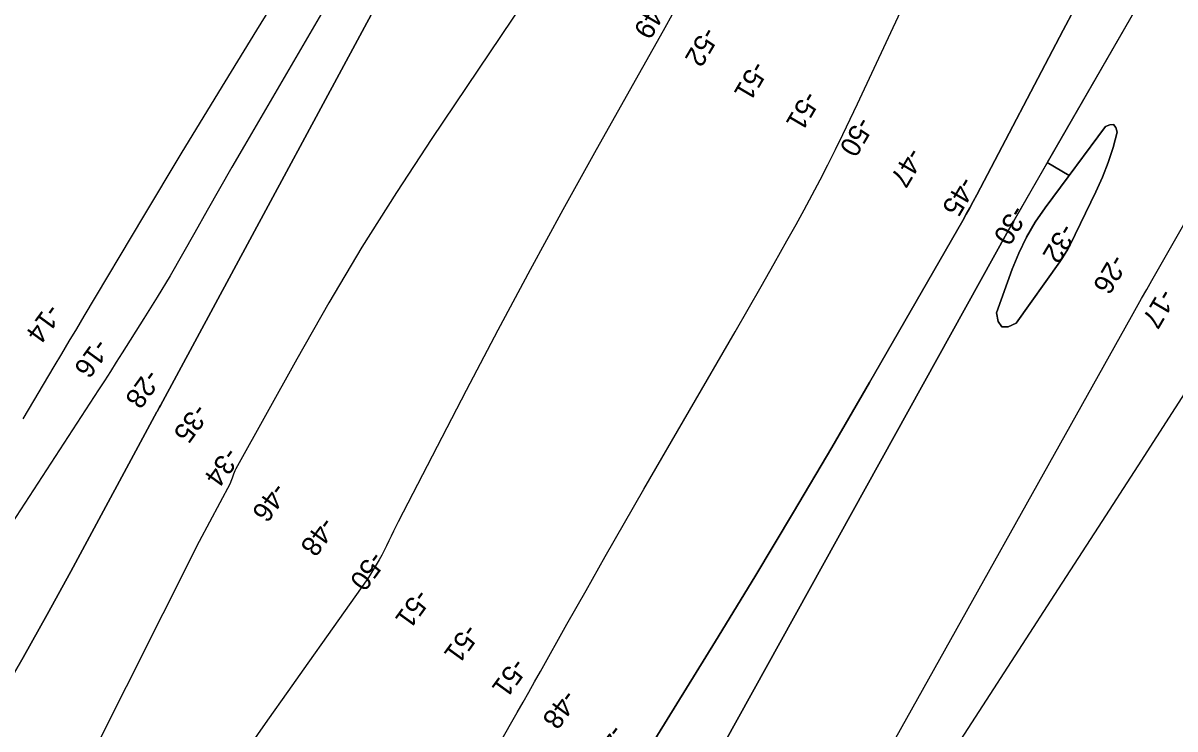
# Model space of a CAD drawing. Extents: x 3888273 to 3909528, y 158682 to 181032.
# Drawn here: x 3897168 to 3899111, y 165430 to 166620 of the extents above; entities that cross this region are included whole.
import ezdxf

# ---------------------------------------------------------------- set-up
doc = ezdxf.new("R2010")
doc.units = 0
for name, color, linetype in [('V-GRID-MAJR', 7, 'Continuous'), ('V-RIVR-RANG', 7, 'Continuous'), ('V-TOPO-DPTH', 7, 'Continuous'), ('V-TOPO-MAJR', 7, 'Continuous'), ('V-TOPO-MINR', 7, 'Continuous')]:
    doc.layers.add(name, color=color, linetype=linetype)

msp = doc.modelspace()

# ---------------------------------------------------------------- linework, layer by layer
at = {"layer": 'V-GRID-MAJR'}
msp.add_spline([(3899339.3, 161091.9), (3899310.2, 162813.4), (3899208, 168873.7), (3899105.7, 174933.9), (3899088.2, 175974.6)], degree=3, dxfattribs=at)
at = {"layer": 'V-TOPO-DPTH'}
for points in [[(3898326, 165362), (3898829.7, 166271.1), (3899231.7, 166968.9)], [(3899231.7, 166968.9), (3898895.1, 166384.7), (3898932.1, 166362.8)], [(3897801.2, 166859.3), (3897541.3, 166413.7), (3897520.1, 166377.2), (3897499.1, 166340.6), (3897478.3, 166303.9), (3897457.7, 166267.1), (3897436.9, 166230.4), (3897415.6, 166194), (3897393.8, 166157.9), (3897371.6, 166122.1), (3897335, 166064.1), (3897325, 166048.4), (3897315, 166032.7), (3897304.9, 166017), (3897294.7, 166001.4), (3897111.5, 165720.4)], [(3897126.3, 165478.6), (3897167.7, 165550.3), (3897208.1, 165622.5), (3897248, 165695), (3897393.6, 165964.4), (3897394.3, 165965.7), (3897395.8, 165968.4), (3897398.1, 165972.4), (3897399.7, 165975), (3897855.6, 166821)], [(3897126.3, 165478.6), (3897167.7, 165550.3), (3897208.1, 165622.5), (3897248, 165695), (3897393.6, 165964.4), (3897394.3, 165965.7), (3897395.8, 165968.4), (3897398.1, 165972.4), (3897399.7, 165975), (3897855.6, 166821)], [(3898051.9, 166714.8), (3897857.4, 166425.7), (3897797.6, 166334.3), (3897739.4, 166242), (3897683.6, 166148.2), (3897629.3, 166053.4), (3897526.5, 165868.1), (3897525, 165865.2), (3897523.6, 165862.2), (3897522.5, 165859.1), (3897521.6, 165856), (3897520.6, 165852.8), (3897519.5, 165849.7), (3897518.2, 165846.7), (3897516.8, 165843.8), (3897464.6, 165746), (3897157, 165133.8)], [(3898051.9, 166714.8), (3897857.4, 166425.7), (3897797.6, 166334.3), (3897739.4, 166242), (3897683.6, 166148.2), (3897629.3, 166053.4), (3897526.5, 165868.1), (3897525, 165865.2), (3897523.6, 165862.2), (3897522.5, 165859.1), (3897521.6, 165856), (3897520.6, 165852.8), (3897519.5, 165849.7), (3897518.2, 165846.7), (3897516.8, 165843.8), (3897464.6, 165746), (3897157, 165133.8)], [(3898959.1, 166678.7), (3898922.1, 166608.2), (3898776.4, 166330.3), (3898770.6, 166319.4), (3898764.8, 166308.6), (3898758.8, 166297.9), (3898752.7, 166287.2), (3898595.5, 166014), (3898531.7, 165904.3), (3898467.3, 165795), (3898401.8, 165686.2), (3898335.7, 165577.9), (3898221.7, 165392.8)], [(3898221.7, 165392.8), (3898335.7, 165577.9), (3898401.8, 165686.2), (3898467.3, 165795), (3898531.7, 165904.3), (3898595.5, 166014), (3898752.7, 166287.2), (3898758.8, 166297.9), (3898764.8, 166308.6), (3898770.6, 166319.4), (3898776.4, 166330.3), (3898922.1, 166608.2), (3898959.1, 166678.7)], [(3898998.1, 166384.8), (3899006.3, 166410.3), (3899013.3, 166436.2), (3899011, 166444.1), (3899007.2, 166448.8), (3899001.1, 166448.7), (3898993.5, 166445.4), (3898891.8, 166308.7), (3898875.2, 166284.2), (3898860.1, 166258.8), (3898847.3, 166232.3), (3898836.1, 166204.9), (3898809.5, 166131.2), (3898812.5, 166116.7), (3898818.5, 166108), (3898829.1, 166108), (3898842.8, 166113.8), (3898916.5, 166217.3), (3898921.3, 166224.2), (3898925.7, 166231.3), (3898929.8, 166238.7), (3898933.7, 166246.1), (3898977.4, 166335.5), (3898988.3, 166360), (3898998.1, 166384.8)], [(3898932.1, 166362.8), (3898993.5, 166445.4), (3899001.1, 166448.7), (3899007.2, 166448.8), (3899011, 166444.1), (3899013.3, 166436.2), (3899006.3, 166410.3), (3898998.1, 166384.8)], [(3898602.9, 165348.4), (3899037.6, 166125.5), (3899046, 166140.6), (3899054.5, 166155.7), (3899063, 166170.7), (3899071.6, 166185.7), (3899185.9, 166385.7)], [(3898930.5, 166360.7), (3898932.1, 166362.8), (3898895.1, 166384.7), (3898893.9, 166382.5), (3898829.7, 166271.1), (3898326, 165362)], [(3898998.1, 166384.8), (3898988.3, 166360), (3898977.4, 166335.5), (3898933.7, 166246.1), (3898929.8, 166238.7), (3898925.7, 166231.3), (3898921.3, 166224.2), (3898916.5, 166217.3), (3898842.8, 166113.8), (3898829.1, 166108), (3898818.5, 166108), (3898812.5, 166116.7), (3898809.5, 166131.2), (3898836.1, 166204.9), (3898847.3, 166232.3), (3898860.1, 166258.8), (3898875.2, 166284.2), (3898891.8, 166308.7), (3898930.5, 166360.7)]]:
    msp.add_lwpolyline(points, dxfattribs=at)
at = {"layer": 'V-TOPO-MAJR'}
for points in [[(3897941.3, 165352.8), (3898001.3, 165457.6), (3898011.1, 165474.7), (3898020.9, 165491.9), (3898030.6, 165509.1), (3898040.3, 165526.3), (3898085.1, 165606.2), (3898117.3, 165663.4), (3898149.7, 165720.4), (3898182.3, 165777.3), (3898215, 165834.1), (3898368.8, 166099.4), (3898390.8, 166137.7), (3898412.8, 166176), (3898434.6, 166214.5), (3898456.3, 166253), (3898471.5, 166280.3), (3898485.3, 166305.3), (3898498.9, 166330.4), (3898512.1, 166355.7), (3898525.1, 166381.1), (3898537.9, 166406.7), (3898550.4, 166432.3), (3898562.8, 166458.1), (3898575, 166483.9), (3898897.2, 167173.5)], [(3898265, 166638.3), (3898247.4, 166607.3), (3898229.9, 166576.3), (3898212.4, 166545.2), (3898134.3, 166406.2), (3898078.3, 166305.4), (3898023, 166204.2), (3897968.7, 166102.4), (3897915.1, 166000.3), (3897800.5, 165779), (3897796.4, 165771), (3897792.4, 165763), (3897788.6, 165754.9), (3897784.8, 165746.7), (3897780.9, 165738.7), (3897776.9, 165730.7), (3897772.7, 165722.8), (3897768.2, 165715), (3897754, 165690.9), (3897752.2, 165688), (3897750.4, 165685.1), (3897748.5, 165682.2), (3897746.5, 165679.4), (3897682.2, 165588.9), (3897648.1, 165540.8), (3897614.1, 165492.7), (3897580.2, 165444.5), (3897546.4, 165396.2)]]:
    msp.add_lwpolyline(points, dxfattribs=at)
at = {"layer": 'V-TOPO-MINR'}
for points in [[(3898326, 165362), (3898829.7, 166271.1), (3899231.7, 166968.9)], [(3897801.2, 166859.3), (3897541.3, 166413.7), (3897520.1, 166377.2), (3897499.1, 166340.6), (3897478.3, 166303.9), (3897457.7, 166267.1), (3897436.9, 166230.4), (3897415.6, 166194), (3897393.8, 166157.9), (3897371.6, 166122.1), (3897335, 166064.1), (3897325, 166048.4), (3897315, 166032.7), (3897304.9, 166017), (3897294.7, 166001.4), (3897111.5, 165720.4)], [(3897855.6, 166821), (3897399.7, 165975), (3897398.1, 165972.4), (3897395.8, 165968.4), (3897394.3, 165965.7), (3897393.6, 165964.4), (3897248, 165695), (3897208.1, 165622.5), (3897167.7, 165550.3), (3897126.3, 165478.6)], [(3898051.9, 166714.8), (3897857.4, 166425.7), (3897797.6, 166334.3), (3897739.4, 166242), (3897683.6, 166148.2), (3897629.3, 166053.4), (3897526.5, 165868.1), (3897525, 165865.2), (3897523.6, 165862.2), (3897522.5, 165859.1), (3897521.6, 165856), (3897520.6, 165852.8), (3897519.5, 165849.7), (3897518.2, 165846.7), (3897516.8, 165843.8), (3897464.6, 165746), (3897157, 165133.8)], [(3897625.4, 166712.1), (3897561.2, 166608.1), (3897497.4, 166503.8), (3897434, 166399.3), (3897371, 166294.5), (3897270.3, 166125.9), (3897257.6, 166104.7), (3897244.9, 166083.5), (3897232.3, 166062.3), (3897219.7, 166041), (3897167.3, 165952.9)], [(3898221.7, 165392.8), (3898335.7, 165577.9), (3898401.8, 165686.2), (3898467.3, 165795), (3898531.7, 165904.3), (3898595.5, 166014), (3898752.7, 166287.2), (3898758.8, 166297.9), (3898764.8, 166308.6), (3898770.6, 166319.4), (3898776.4, 166330.3), (3898922.1, 166608.2), (3898959.1, 166678.7)], [(3898998.1, 166384.8), (3899006.3, 166410.3), (3899013.3, 166436.2), (3899011, 166444.1), (3899007.2, 166448.8), (3899001.1, 166448.7), (3898993.5, 166445.4), (3898891.8, 166308.7), (3898875.2, 166284.2), (3898860.1, 166258.8), (3898847.3, 166232.3), (3898836.1, 166204.9), (3898809.5, 166131.2), (3898812.5, 166116.7), (3898818.5, 166108), (3898829.1, 166108), (3898842.8, 166113.8), (3898916.5, 166217.3), (3898921.3, 166224.2), (3898925.7, 166231.3), (3898929.8, 166238.7), (3898933.7, 166246.1), (3898977.4, 166335.5), (3898988.3, 166360), (3898998.1, 166384.8)], [(3898602.9, 165348.4), (3899037.6, 166125.5), (3899046, 166140.6), (3899054.5, 166155.7), (3899063, 166170.7), (3899071.6, 166185.7), (3899185.9, 166385.7)], [(3898575, 165142.2), (3898780.4, 165459.1), (3898847.5, 165562.6), (3898914.5, 165666.1), (3898981.5, 165769.7), (3899048.4, 165873.3), (3899174.8, 166069)]]:
    msp.add_lwpolyline(points, dxfattribs=at)

# ---------------------------------------------------------------- texts
at = {"layer": 'V-RIVR-RANG'}
for s, rotation, p in [('-49', 239.5561, (3898229.3, 166663)), ('-52', 239.5561, (3898315.6, 166616)), ('-51', 239.5561, (3898398.5, 166558.6)), ('-51', 239.5561, (3898486.2, 166508)), ('-50', 239.5561, (3898576.4, 166464.4)), ('-47', 239.5561, (3898661.3, 166412.5)), ('-45', 239.5561, (3898749.5, 166363.7)), ('-30', 239.5561, (3898836.2, 166315.3)), ('-32', 239.4183, (3898918.9, 166284.5)), ('-26', 239.4183, (3899004.3, 166232.5)), ('-17', 239.4183, (3899086.2, 166174.5)), ('-14', 233.8983, (3897209.4, 166149.1)), ('-16', 233.8983, (3897290.4, 166090.5)), ('-28', 233.8983, (3897376.5, 166038.8)), ('-35', 233.8983, (3897457.9, 165980.7)), ('-34', 234.0448, (3897510, 165907.1)), ('-46', 234.0448, (3897590.4, 165847.5)), ('-48', 234.0448, (3897672, 165789.6)), ('-50', 234.0448, (3897755.2, 165731.7)), ('-51', 234.0448, (3897831.7, 165668)), ('-51', 234.0448, (3897914.1, 165609.1)), ('-51', 234.0448, (3897994.8, 165551.6)), ('-48', 234.0448, (3898080.1, 165498.2)), ('-47', 234.0448, (3898159.8, 165439.8))]:
    msp.add_text(s, height=33.5, rotation=rotation, dxfattribs=at).set_placement(p)

doc.saveas('drawing.dxf')
